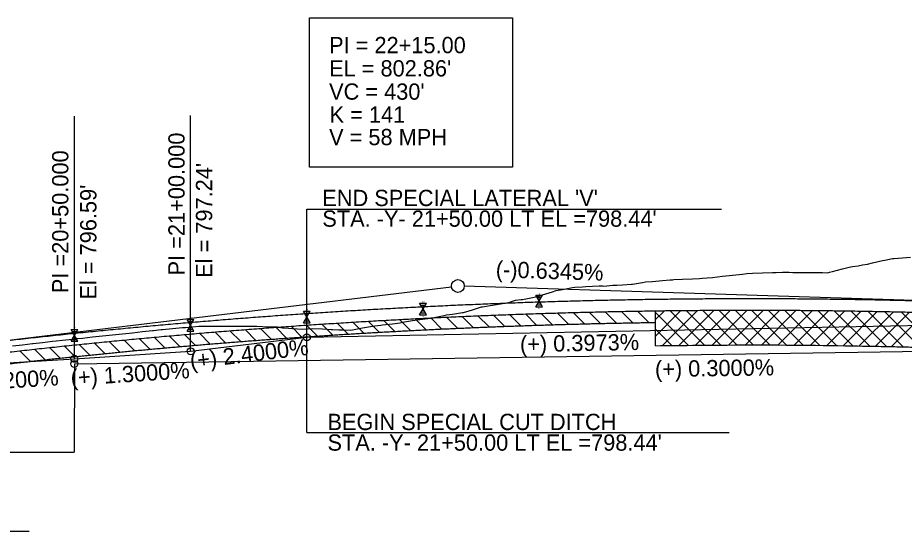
# Model space of a CAD drawing. Extents: x 579185 to 595036, y -53221 to -44640.
# Drawn here: x 580351.9 to 580733.3, y -46961.8 to -46740.9 of the extents above; entities that cross this region are included whole.
import ezdxf

# ---------------------------------------------------------------- set-up
doc = ezdxf.new("R2010")
doc.units = 0
for name, color, linetype in [('Exist Vertical Profile Ground Line', 7, 'Continuous'), ('Old_Level_2', 7, 'Continuous'), ('Prop Grid Mask', 7, 'Continuous'), ('Prop Hatching', 7, 'Continuous'), ('Prop Vertical Profile Curve Label', 7, 'Continuous'), ('Prop Vertical Profile Ditch Grade Left', 7, 'Continuous'), ('Prop Vertical Profile Ditch Grade Left Label', 7, 'Continuous'), ('Prop Vertical Profile Ditch Grade Right', 7, 'Continuous'), ('Prop Vertical Profile Ditch Grade Right Label', 7, 'Continuous'), ('Prop Vertical Profile Grade', 7, 'Continuous'), ('Prop Vertical Profile Grade Label', 7, 'Continuous'), ('Prop VPI Ditch Grade Right Label', 7, 'Continuous'), ('Prop VPI Label', 7, 'Continuous'), ('Scratch_Level_1', 7, 'Continuous')]:
    doc.layers.add(name, color=color, linetype=linetype)

msp = doc.modelspace()

# ---------------------------------------------------------------- linework, layer by layer
at = {"layer": 'Exist Vertical Profile Ground Line'}
for points in [[(580529.41, -46870.14), (580530.29, -46869.96), (580534.6, -46869.11), (580536.37, -46868.75), (580538.9, -46868.39), (580543.2, -46867.76), (580543.7, -46867.69), (580547.51, -46866.49), (580551.4, -46865.26), (580551.81, -46865.19), (580555.2, -46864.62), (580556.11, -46864.47), (580560.42, -46863.79), (580562.22, -46863.5), (580563.16, -46863.32), (580564.72, -46862.85), (580566.1, -46862.44), (580568.44, -46862.11), (580569.02, -46862.04), (580569.79, -46861.96), (580573.33, -46861.22), (580575.88, -46860.7), (580577.63, -46860.14), (580581.93, -46858.77), (580583.57, -46858.25), (580586.24, -46857.76), (580590.54, -46856.95), (580591.55, -46856.76), (580594.84, -46856.64), (580596.32, -46856.58), (580599.15, -46856.42), (580602.1, -46856.26), (580603.45, -46856.29), (580604.06, -46856.3), (580607.87, -46855.95), (580609.68, -46855.98), (580612.06, -46855.8), (580615.98, -46855.52), (580616.36, -46855.46), (580620.66, -46854.77), (580622.04, -46854.55), (580624.97, -46854.3), (580629.27, -46853.93), (580632.65, -46853.65), (580633.14, -46853.64), (580633.57, -46853.6), (580634.12, -46853.55), (580637.88, -46853.38), (580642.18, -46853.2), (580645.18, -46853.07), (580646.48, -46852.97), (580648.45, -46852.82), (580650.78, -46852.57), (580655.09, -46852.1), (580659.39, -46851.64), (580663.69, -46851.16), (580665.58, -46850.89), (580668, -46850.82), (580672.3, -46850.69), (580676.6, -46850.56), (580678.13, -46850.52), (580680.91, -46850.4), (580681.56, -46850.37), (580682.81, -46850.4), (580683.82, -46850.41), (580685.36, -46850.46), (580689.51, -46850.47), (580692.48, -46850.48), (580693.46, -46850.44), (580693.82, -46850.44), (580697.57, -46850.53), (580698.12, -46850.55), (580700.23, -46850.6), (580701.17, -46850.38), (580702.42, -46850.05), (580706.73, -46848.91), (580709.55, -46848.17), (580711.03, -46847.94), (580713.43, -46847.56), (580715.33, -46847.25), (580717.51, -46846.9), (580719.64, -46846.4), (580723.94, -46845.39), (580724.93, -46845.16), (580728.24, -46844.54), (580728.78, -46844.45), (580732.55, -46844.17), (580735.95, -46843.92)], [(580349.56, -46882.05), (580353.86, -46881.56), (580358.16, -46881.07), (580358.55, -46881.03), (580362.47, -46880.57), (580366.77, -46880.06), (580368.41, -46879.87), (580371.07, -46879.58), (580375.38, -46879.12), (580377.2, -46878.93), (580379.68, -46878.67), (580383.98, -46878.22), (580388.29, -46877.77), (580392.59, -46877.31), (580396.89, -46876.85), (580401.2, -46876.39), (580405.5, -46875.93), (580409.8, -46875.47), (580410.32, -46875.41), (580413.55, -46875.07), (580414.11, -46875.02), (580418.41, -46874.61), (580422.71, -46874.19), (580424.03, -46874.07), (580425.42, -46873.95), (580427.02, -46873.79), (580429.76, -46873.52), (580431.32, -46873.52), (580435.62, -46873.53), (580439.93, -46873.54), (580444.23, -46873.56), (580448.53, -46873.6), (580449.15, -46873.6), (580452.84, -46873.57), (580454.73, -46873.56), (580457.14, -46873.64), (580461.44, -46873.8), (580463.7, -46873.89), (580465.75, -46874.25), (580466.52, -46874.23), (580470.05, -46874.51), (580474.35, -46874.86), (580478.82, -46874.5), (580482.96, -46874.74), (580486.7, -46874.96), (580487.26, -46874.99), (580490.03, -46875.13), (580491.06, -46875.17), (580491.57, -46875.18), (580495.05, -46875.26), (580495.87, -46875.11), (580500.17, -46874.34), (580504.47, -46873.56), (580505.57, -46873.39), (580508.09, -46873.12), (580508.78, -46873.04), (580513.08, -46872.52), (580516.47, -46872.1), (580517.38, -46871.88), (580518.27, -46871.67), (580521.69, -46871.06), (580525.99, -46870.55), (580529.41, -46870.14)]]:
    msp.add_lwpolyline(points, dxfattribs=at)
at = {"layer": 'Old_Level_2'}
for p, q in [((580576.24, -46862.7), (580574.79, -46860.2)), ((580574.79, -46860.2), (580577.68, -46860.2)), ((580574.79, -46865.2), (580576.24, -46862.7)), ((580575.27, -46861.04), (580577.2, -46861.04)), ((580575.76, -46861.87), (580576.72, -46861.87)), ((580576.24, -46862.7), (580577.68, -46860.2)), ((580577.68, -46865.21), (580576.24, -46862.7)), ((580526.24, -46866.15), (580524.79, -46863.65)), ((580524.79, -46863.65), (580527.68, -46863.65)), ((580524.79, -46868.65), (580526.24, -46866.15)), ((580525.27, -46864.49), (580527.2, -46864.49)), ((580525.76, -46865.32), (580526.72, -46865.32)), ((580526.24, -46866.15), (580527.68, -46863.65)), ((580527.68, -46868.66), (580526.24, -46866.15)), ((580574.79, -46865.2), (580577.68, -46865.21)), ((580575.27, -46864.37), (580577.2, -46864.37)), ((580575.75, -46863.54), (580576.72, -46863.54)), ((580476.24, -46869.57), (580474.79, -46867.07)), ((580474.79, -46867.07), (580477.68, -46867.07)), ((580474.79, -46872.07), (580476.24, -46869.57)), ((580475.27, -46867.91), (580477.2, -46867.91)), ((580475.75, -46870.41), (580476.72, -46870.41)), ((580475.76, -46868.74), (580476.72, -46868.74)), ((580476.24, -46869.57), (580477.68, -46867.07)), ((580477.68, -46872.08), (580476.24, -46869.57)), ((580524.79, -46868.65), (580527.68, -46868.66)), ((580525.27, -46867.82), (580527.2, -46867.82)), ((580525.75, -46866.99), (580526.72, -46866.99)), ((580426.24, -46873.16), (580424.79, -46870.66)), ((580424.79, -46870.66), (580427.68, -46870.66)), ((580424.79, -46875.66), (580426.24, -46873.16)), ((580425.27, -46871.49), (580427.2, -46871.49)), ((580425.75, -46873.99), (580426.72, -46873.99)), ((580425.76, -46872.33), (580426.72, -46872.33)), ((580426.24, -46873.16), (580427.68, -46870.66)), ((580427.68, -46875.66), (580426.24, -46873.16)), ((580474.79, -46872.07), (580477.68, -46872.08)), ((580475.27, -46871.24), (580477.2, -46871.24)), ((580376.24, -46877.56), (580374.79, -46875.06)), ((580374.79, -46875.06), (580377.68, -46875.06)), ((580374.79, -46880.06), (580376.24, -46877.56)), ((580375.27, -46875.9), (580377.2, -46875.9)), ((580375.76, -46876.73), (580376.72, -46876.73)), ((580376.24, -46877.56), (580377.68, -46875.06)), ((580377.68, -46880.07), (580376.24, -46877.56)), ((580424.79, -46875.66), (580427.68, -46875.66)), ((580425.27, -46874.83), (580427.2, -46874.83)), ((580374.79, -46880.06), (580377.68, -46880.07)), ((580375.27, -46879.23), (580377.2, -46879.23)), ((580375.75, -46878.4), (580376.72, -46878.4))]:
    msp.add_line(p, q, dxfattribs=at)
at = {"layer": 'Prop Grid Mask'}
msp.add_lwpolyline([(580477.44, -46740.95), (580564.8, -46740.95), (580564.8, -46805.13), (580477.44, -46805.13)], close=True, dxfattribs=at)
at = {"layer": 'Prop Hatching'}
for p, q in [((580629.22, -46881.93), (580644.39, -46866.76)), ((580636.38, -46881.84), (580651.5, -46866.72)), ((580643.52, -46881.77), (580658.6, -46866.69)), ((580646.48, -46866.75), (580661.41, -46881.68)), ((580650.64, -46881.72), (580665.69, -46866.68)), ((580653.51, -46866.71), (580668.48, -46881.68)), ((580657.74, -46881.69), (580672.75, -46866.68)), ((580660.56, -46866.68), (580675.57, -46881.69)), ((580664.83, -46881.68), (580679.8, -46866.71)), ((580667.62, -46866.68), (580682.67, -46881.72)), ((580671.9, -46881.68), (580686.83, -46866.75)), ((580674.71, -46866.69), (580689.79, -46881.77)), ((580681.81, -46866.72), (580696.93, -46881.84)), ((580688.92, -46866.76), (580704.09, -46881.92)), ((580626.24, -46877.84), (580637.25, -46866.83)), ((580626.24, -46870.77), (580630.09, -46866.91)), ((580626.24, -46881.97), (580626.24, -46866.97)), ((580626.24, -46867.72), (580640.32, -46881.8)), ((580632.48, -46866.88), (580647.33, -46881.74)), ((580639.47, -46866.81), (580654.37, -46881.7)), ((580678.95, -46881.7), (580693.84, -46866.81)), ((580685.98, -46881.74), (580700.84, -46866.88)), ((580692.99, -46881.8), (580707.81, -46866.97)), ((580696.06, -46866.83), (580711.26, -46882.03)), ((580699.99, -46881.87), (580714.77, -46867.09)), ((580703.21, -46866.91), (580718.46, -46882.15)), ((580706.97, -46881.96), (580721.72, -46867.21)), ((580710.39, -46867.01), (580725.67, -46882.3)), ((580713.93, -46882.07), (580728.65, -46867.36)), ((580717.58, -46867.13), (580732.9, -46882.46)), ((580720.87, -46882.2), (580735.56, -46867.52)), ((580724.79, -46867.27), (580740.15, -46882.64)), ((580727.8, -46882.34), (580742.45, -46867.69)), ((580732.02, -46867.43), (580747.43, -46882.84)), ((580626.24, -46874.79), (580633.32, -46881.87)), ((580626.24, -46881.86), (580626.34, -46881.97))]:
    msp.add_line(p, q, dxfattribs=at)
msp.add_spline([(580626.24, -46866.97), (580627.31, -46866.95), (580635.89, -46866.84), (580644.48, -46866.76), (580653.06, -46866.71), (580661.65, -46866.68), (580670.23, -46866.68), (580678.82, -46866.7), (580687.4, -46866.75), (580695.98, -46866.83), (580704.57, -46866.93), (580713.15, -46867.06), (580721.74, -46867.21), (580730.32, -46867.39), (580738.91, -46867.6), (580747.49, -46867.83), (580756.09, -46868.09)], degree=3, dxfattribs=at)
msp.add_open_spline([(580626.24, -46881.97), (580632.55, -46881.88), (580638.87, -46881.81), (580668.09, -46881.58), (580691, -46881.69), (580719.22, -46882.16), (580724.54, -46882.27), (580732.41, -46882.44), (580734.96, -46882.51), (580738.72, -46882.6), (580739.93, -46882.63), (580742.38, -46882.7), (580743.63, -46882.73), (580745.53, -46882.78), (580746.18, -46882.8), (580747.17, -46882.83), (580747.53, -46882.84), (580748.23, -46882.86), (580748.58, -46882.87), (580749.64, -46882.91), (580750.35, -46882.93), (580752.46, -46882.99), (580753.87, -46883.03), (580755.4, -46883.08), (580755.52, -46883.08), (580755.63, -46883.09)], degree=3, dxfattribs=at)
at = {"layer": 'Prop Vertical Profile Ditch Grade Left'}
msp.add_line((580476.24, -46878.35), (580851.24, -46870.9), dxfattribs=at)
msp.add_lwpolyline([(580326.24, -46890.65), (580376.24, -46887.6), (580426.24, -46884.35), (580476.24, -46878.35)], dxfattribs=at)
at = {"layer": 'Prop Vertical Profile Ditch Grade Left Label'}
for p, q in [((580376.24, -46887.6), (580376.24, -46783.31)), ((580426.24, -46884.35), (580426.24, -46783.02)), ((580476.24, -46823.2), (580654.73, -46823.2)), ((580476.24, -46878.35), (580476.24, -46823.2)), ((580476.24, -46919.36), (580476.24, -46878.35)), ((580476.24, -46919.36), (580657.98, -46919.36))]:
    msp.add_line(p, q, dxfattribs=at)
for centre in [(580476.24, -46878.35), (580426.24, -46884.35), (580376.24, -46887.6)]:
    msp.add_circle(centre, 1.5, dxfattribs=at)
at = {"layer": 'Prop Vertical Profile Ditch Grade Right'}
msp.add_line((580376.24, -46889.8), (580876.24, -46882.3), dxfattribs=at)
at = {"layer": 'Prop Vertical Profile Ditch Grade Right Label'}
for p, q in [((580376.24, -46889.8), (580376.2, -46927.7)), ((580196.09, -46927.7), (580376.2, -46927.7)), ((580176.2, -46961.75), (580356.78, -46961.75))]:
    msp.add_line(p, q, dxfattribs=at)
at = {"layer": 'Prop Vertical Profile Grade'}
msp.add_spline([(580326.24, -46882.21), (580334.84, -46881.19), (580343.44, -46880.19), (580352.04, -46879.22), (580360.64, -46878.27), (580369.24, -46877.35), (580377.84, -46876.46), (580386.44, -46875.59), (580395.04, -46874.75), (580403.64, -46873.93), (580412.24, -46873.15), (580420.84, -46872.38), (580429.44, -46871.65), (580438.04, -46870.94), (580446.64, -46870.25), (580455.24, -46869.6), (580463.84, -46868.97), (580472.44, -46868.36), (580481.04, -46867.78), (580489.64, -46867.23), (580498.24, -46866.7), (580506.84, -46866.2), (580515.44, -46865.73), (580524.04, -46865.28), (580532.64, -46864.86), (580541.24, -46864.46), (580549.84, -46864.09), (580558.44, -46863.75), (580567.04, -46863.43), (580575.64, -46863.14), (580584.24, -46862.88), (580592.84, -46862.64), (580601.44, -46862.43), (580610.04, -46862.24), (580618.64, -46862.08), (580627.24, -46861.95), (580635.84, -46861.84), (580644.44, -46861.76), (580653.04, -46861.71), (580661.64, -46861.68), (580670.24, -46861.68), (580678.84, -46861.7), (580687.44, -46861.75), (580696.04, -46861.83), (580704.64, -46861.93), (580713.24, -46862.06), (580721.84, -46862.21), (580730.44, -46862.39), (580739.04, -46862.6), (580747.64, -46862.84), (580756.24, -46863.1)], degree=3, dxfattribs=at)
at = {"layer": 'Prop VPI Ditch Grade Right Label'}
msp.add_circle((580376.24, -46889.8), 1.5, dxfattribs=at)
at = {"layer": 'Prop VPI Label'}
for p, q in [((580326.24, -46882.21), (580538.51, -46856.6)), ((580756.24, -46863.1), (580543.99, -46856.36))]:
    msp.add_line(p, q, dxfattribs=at)
msp.add_circle((580541.24, -46856.27), 2.75, dxfattribs=at)
at = {"layer": 'Scratch_Level_1'}
for p, q in [((580522.81, -46870.35), (580527.57, -46875.12)), ((580529.54, -46870.01), (580534.32, -46874.79)), ((580536.29, -46869.69), (580541.08, -46874.48)), ((580543.06, -46869.39), (580547.85, -46874.19)), ((580549.84, -46869.1), (580554.65, -46873.91)), ((580556.64, -46868.82), (580561.45, -46873.64)), ((580563.45, -46868.57), (580568.28, -46873.4)), ((580570.28, -46868.32), (580575.12, -46873.17)), ((580577.12, -46868.1), (580581.98, -46872.95)), ((580583.98, -46867.89), (580588.85, -46872.75)), ((580590.86, -46867.7), (580595.74, -46872.57)), ((580597.76, -46867.52), (580602.64, -46872.4)), ((580604.67, -46867.36), (580609.56, -46872.26)), ((580611.59, -46867.21), (580616.5, -46872.12)), ((580618.54, -46867.09), (580623.46, -46872.01)), ((580626.24, -46871.97), (580626.24, -46866.97)), ((580462.86, -46874.05), (580467.54, -46878.73)), ((580469.47, -46873.58), (580474.15, -46878.27)), ((580476.08, -46873.12), (580480.78, -46877.82)), ((580482.71, -46872.68), (580487.42, -46877.39)), ((580489.36, -46872.26), (580494.07, -46876.97)), ((580496.02, -46871.85), (580500.74, -46876.57)), ((580502.69, -46871.45), (580507.43, -46876.18)), ((580509.38, -46871.07), (580514.13, -46875.81)), ((580516.09, -46870.7), (580520.84, -46875.46)), ((580417.05, -46877.74), (580421.67, -46882.35)), ((580423.56, -46877.17), (580428.18, -46881.79)), ((580430.07, -46876.61), (580434.7, -46881.24)), ((580436.6, -46876.07), (580441.24, -46880.71)), ((580443.15, -46875.54), (580447.8, -46880.19)), ((580449.71, -46875.03), (580454.36, -46879.69)), ((580456.28, -46874.53), (580460.95, -46879.2)), ((580378.33, -46881.43), (580382.89, -46886)), ((580384.75, -46880.78), (580389.32, -46885.35)), ((580391.18, -46880.15), (580395.76, -46884.73)), ((580397.63, -46879.52), (580402.22, -46884.11)), ((580404.09, -46878.91), (580408.69, -46883.51)), ((580410.57, -46878.32), (580415.17, -46882.92)), ((580352.77, -46884.17), (580357.3, -46888.69)), ((580359.14, -46883.46), (580363.68, -46888)), ((580365.52, -46882.77), (580370.07, -46887.32)), ((580371.92, -46882.1), (580376.47, -46886.65))]:
    msp.add_line(p, q, dxfattribs=at)
msp.add_spline([(580326.83, -46887.18), (580335.42, -46886.15), (580344.01, -46885.16), (580352.59, -46884.19), (580361.18, -46883.24), (580369.76, -46882.32), (580378.35, -46881.43), (580386.93, -46880.57), (580395.52, -46879.73), (580404.1, -46878.91), (580412.69, -46878.13), (580421.27, -46877.37), (580429.86, -46876.63), (580438.44, -46875.92), (580447.03, -46875.24), (580455.61, -46874.58), (580464.2, -46873.95), (580472.78, -46873.35), (580481.36, -46872.77), (580489.95, -46872.22), (580498.53, -46871.69), (580507.12, -46871.19), (580515.7, -46870.72), (580524.29, -46870.27), (580532.87, -46869.85), (580541.46, -46869.46), (580550.04, -46869.09), (580558.63, -46868.75), (580567.21, -46868.43), (580575.8, -46868.14), (580584.38, -46867.88), (580592.97, -46867.64), (580601.55, -46867.43), (580610.14, -46867.24), (580618.72, -46867.08), (580626.24, -46866.97)], degree=3, dxfattribs=at)
msp.add_open_spline([(580327.42, -46892.14), (580330.28, -46891.8), (580333.14, -46891.46), (580336, -46891.12), (580338.86, -46890.78), (580341.72, -46890.45), (580344.57, -46890.12), (580347.43, -46889.8), (580350.29, -46889.47), (580353.14, -46889.15), (580356, -46888.84), (580358.86, -46888.52), (580361.71, -46888.21), (580364.57, -46887.9), (580367.43, -46887.6), (580370.28, -46887.3), (580373.14, -46886.99), (580376, -46886.7), (580378.85, -46886.41), (580381.71, -46886.11), (580384.57, -46885.83), (580387.42, -46885.54), (580390.28, -46885.26), (580393.14, -46884.98), (580395.99, -46884.7), (580398.85, -46884.43), (580401.71, -46884.16), (580404.56, -46883.89), (580407.42, -46883.63), (580410.28, -46883.36), (580413.13, -46883.11), (580415.99, -46882.85), (580418.85, -46882.6), (580421.7, -46882.35), (580424.56, -46882.1), (580427.42, -46881.85), (580430.27, -46881.61), (580433.13, -46881.37), (580435.99, -46881.14), (580438.84, -46880.91), (580441.7, -46880.67), (580444.56, -46880.45), (580447.41, -46880.22), (580450.27, -46880), (580453.13, -46879.78), (580455.98, -46879.57), (580458.84, -46879.35), (580461.7, -46879.15), (580464.55, -46878.94), (580467.41, -46878.73), (580470.27, -46878.53), (580473.12, -46878.34), (580475.98, -46878.14), (580478.84, -46877.95), (580481.69, -46877.76), (580484.55, -46877.57), (580487.41, -46877.39), (580490.26, -46877.21), (580493.12, -46877.03), (580495.98, -46876.86), (580498.83, -46876.68), (580501.69, -46876.51), (580504.55, -46876.35), (580507.4, -46876.19), (580510.26, -46876.02), (580513.11, -46875.87), (580515.97, -46875.71), (580518.83, -46875.56), (580521.68, -46875.41), (580524.54, -46875.27), (580527.4, -46875.12), (580530.25, -46874.98), (580533.11, -46874.85), (580535.97, -46874.71), (580538.82, -46874.58), (580541.68, -46874.45), (580544.54, -46874.33), (580547.39, -46874.2), (580550.25, -46874.09), (580553.11, -46873.97), (580555.96, -46873.85), (580558.82, -46873.74), (580561.68, -46873.63), (580564.53, -46873.53), (580567.39, -46873.43), (580570.25, -46873.33), (580573.1, -46873.23), (580575.96, -46873.14), (580578.82, -46873.05), (580581.67, -46872.96), (580584.53, -46872.88), (580587.39, -46872.79), (580590.24, -46872.71), (580593.1, -46872.64), (580595.95, -46872.56), (580598.81, -46872.49), (580601.67, -46872.43), (580604.52, -46872.36), (580607.38, -46872.3), (580610.24, -46872.24), (580613.09, -46872.18), (580615.95, -46872.13), (580618.81, -46872.08), (580621.26, -46872.04), (580623.71, -46872), (580626.16, -46871.97)], degree=3, dxfattribs=at)

# ---------------------------------------------------------------- texts
at = {"layer": 'Old_Level_2'}
for p in [(580526.01, -46863.5), (580576.01, -46860.05), (580476.01, -46866.92), (580575.81, -46866.21), (580426.01, -46870.5), (580525.81, -46869.66), (580376.01, -46874.91), (580475.81, -46873.08), (580425.81, -46876.66), (580375.81, -46881.07)]:
    msp.add_text('6"', height=0.8, dxfattribs=at).set_placement(p)
at = {"layer": 'Prop Vertical Profile Curve Label'}
for s, p in [("VC = 430'", (580485.83, -46776.2)), ('K = 141', (580486.06, -46786.09)), ('V = 58 MPH', (580485.83, -46795.75))]:
    msp.add_text(s, height=7, dxfattribs=at).set_placement(p)
at = {"layer": 'Prop Vertical Profile Ditch Grade Left'}
for s, rotation, p in [('PI =21+00.000', 90, (580423.66, -46851.75)), ('PI =20+50.000', 90, (580373.64, -46859.38)), ("El = 797.24'", 90, (580435.52, -46852.78)), ("El = 796.59'", 90, (580385.72, -46862.13)), ('(+) 0.3973%', 1.1381, (580568.03, -46884.82)), ('(+) 2.4000%', 6.8428, (580426.37, -46891.98)), ('(+) 1.3000%', 3.719, (580374.86, -46899.24)), ('(+) 1.2200%', 3.4907, (580318.45, -46902.12))]:
    msp.add_text(s, height=7, rotation=rotation, dxfattribs=at).set_placement(p)
at = {"layer": 'Prop Vertical Profile Ditch Grade Left Label'}
for s, p in [("END SPECIAL LATERAL 'V'", (580482.92, -46821.94)), ("STA. -Y- 21+50.00 LT EL =798.44'", (580482.92, -46830.81)), ('BEGIN SPECIAL CUT DITCH', (580485.14, -46918.24)), ("STA. -Y- 21+50.00 LT EL =798.44'", (580485.14, -46927.11))]:
    msp.add_text(s, height=7, dxfattribs=at).set_placement(p)
at = {"layer": 'Prop Vertical Profile Ditch Grade Right'}
msp.add_text('(+) 0.3000%', height=7, rotation=0.8594, dxfattribs=at).set_placement((580626.1, -46895.49))
at = {"layer": 'Prop Vertical Profile Grade Label'}
msp.add_text('(-)0.6345%', height=7, rotation=358.1828, dxfattribs=at).set_placement((580557.48, -46852.55))
at = {"layer": 'Prop VPI Label'}
for s, p in [('PI = 22+15.00', (580485.83, -46756.2)), ("EL = 802.86'", (580485.83, -46766.2))]:
    msp.add_text(s, height=7, dxfattribs=at).set_placement(p)

doc.saveas('drawing.dxf')
